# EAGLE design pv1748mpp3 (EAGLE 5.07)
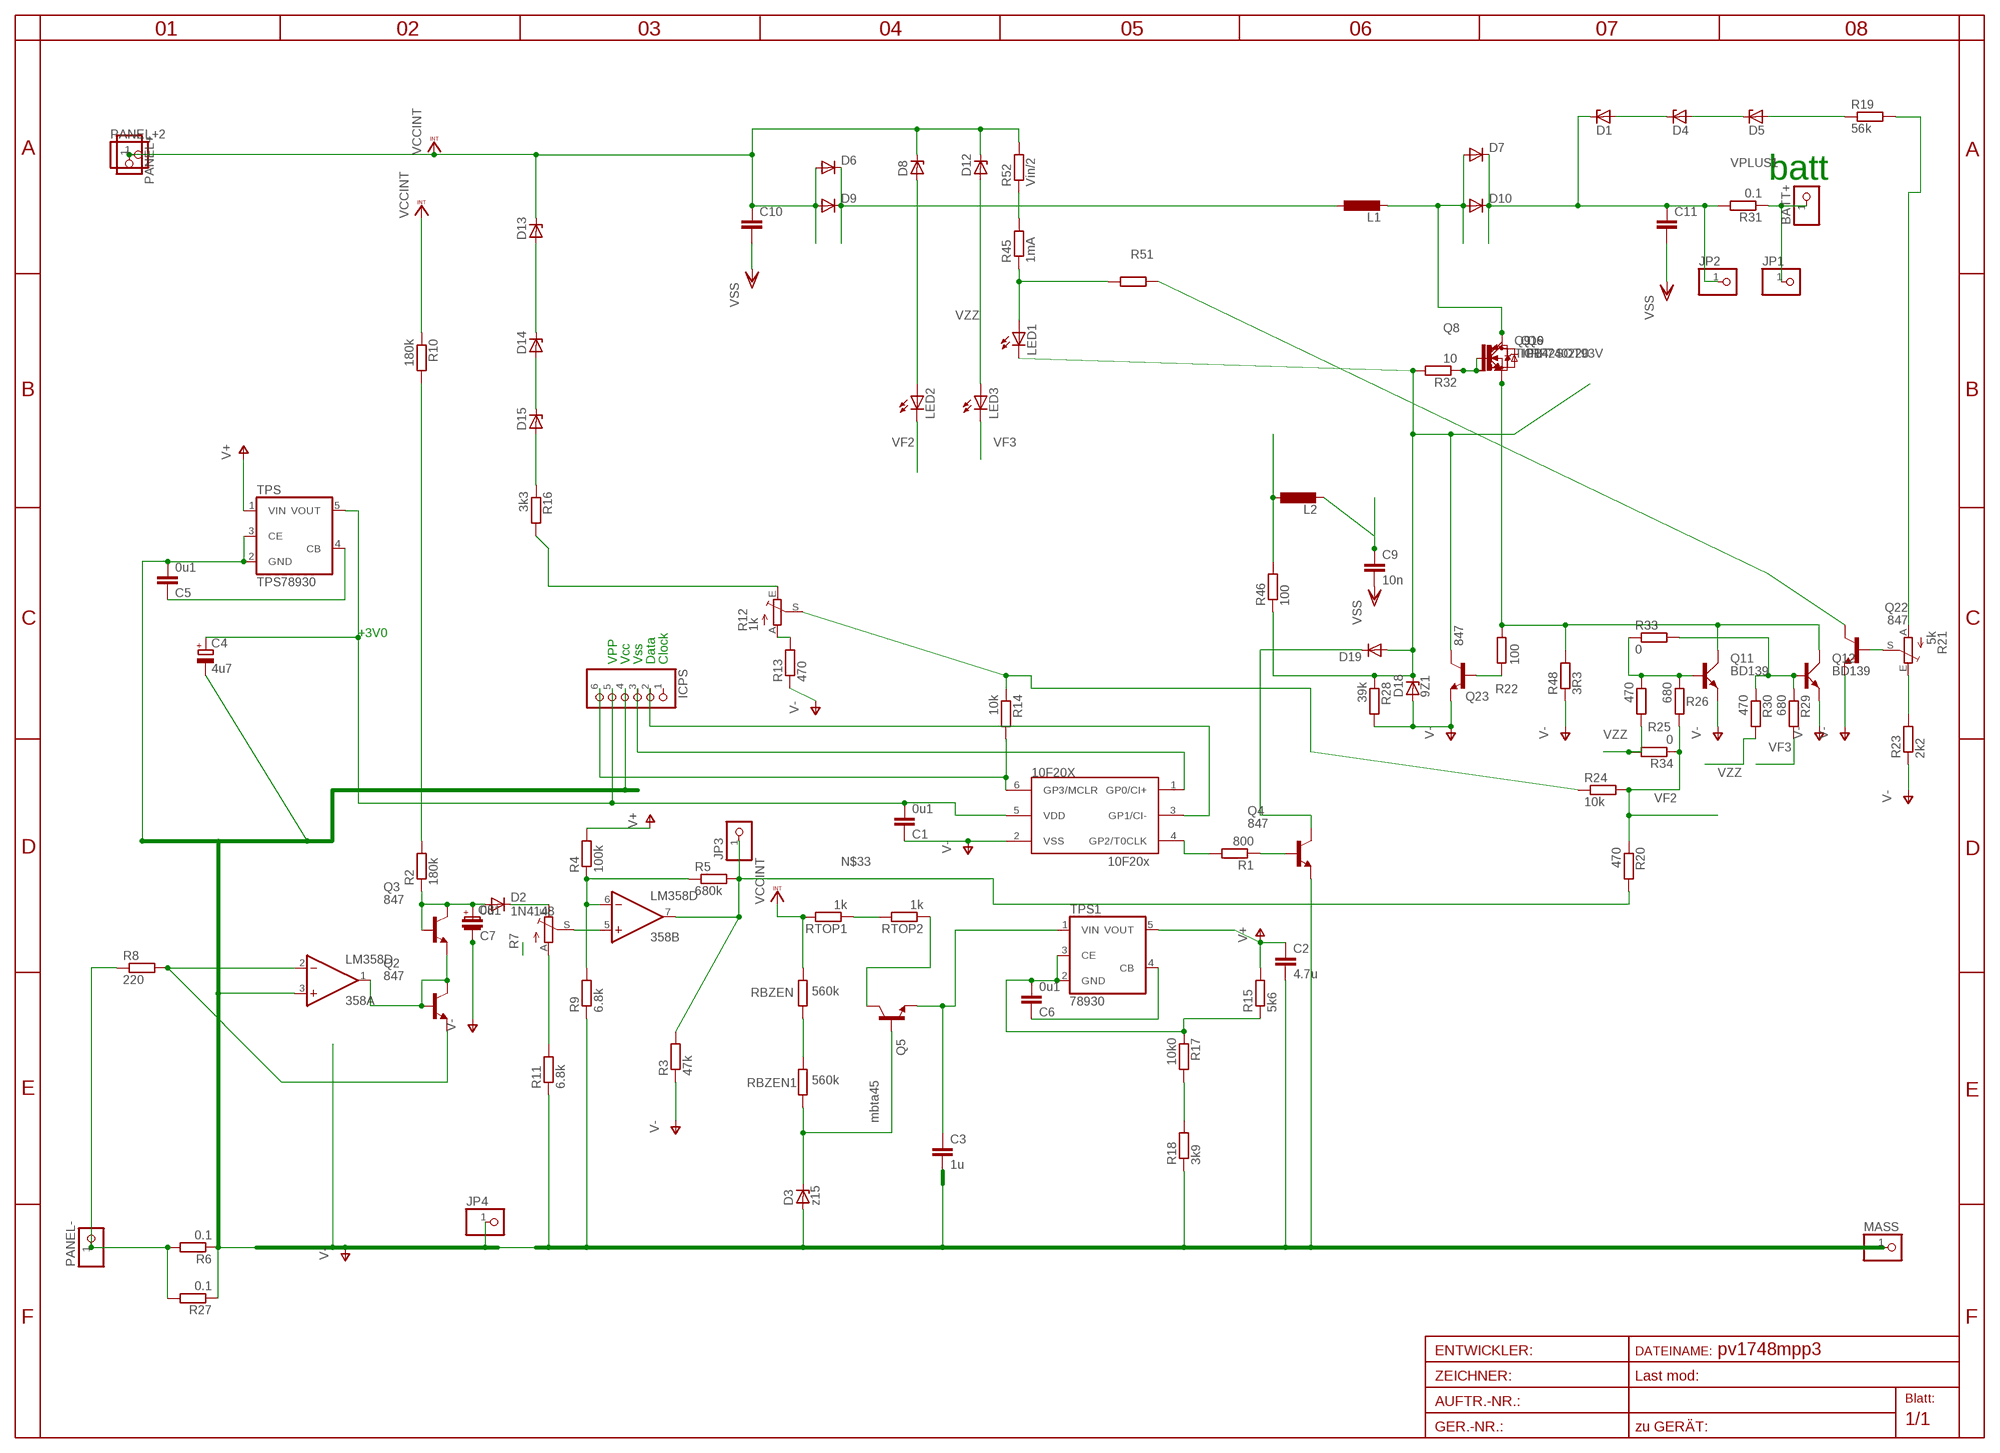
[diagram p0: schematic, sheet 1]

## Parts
10F20X  10F20x  PIC10F204OT  [SOT23-6]
358  LM358D  [SO08]
BATT+  PINHD-1X12MM3  [1X2MM3]
C1  0u1  C-EUC1206  [C1206]
C2  4.7u  C-EUC1206  [C1206]
C3  1u  C-EUC1206  [C1206]
C4  4u7  CPOL-EUSMCA  [SMC_A]
C5  0u1  C-EUC0805  [C0805]
C6  0u1  C-EUC0805  [C0805]
C7  0u1  C-EUC1608  [C1608]
C8  CPOL-EUSMCA  [SMC_A]
C9  10n  C-EUC0805  [C0805]
C10  C-EU075-052X106  [C075-052X106]
C11  C-EU075-052X106  [C075-052X106]
D1  ZENER-DIODESOD80C  [SOD80C]
D2  1N4148  DIODE-SOD80C  [SOD80C]
D3  z15  ZENER-DIODESOD80C  [SOD80C]
D4  ZENER-DIODESOD80C  [SOD80C]
D5  ZENER-DIODESOD80C  [SOD80C]
D6  DIODE-SMC  [SMC]
D7  DIODE-SMC  [SMC]
D8  ZENER-DIODESOD80C  [SOD80C]
D9  DIODE-SMC  [SMC]
D10  DIODE-SMC  [SMC]
D12  ZENER-DIODESOD80C  [SOD80C]
D13  ZENER-DIODESOD80C  [SOD80C]
D14  ZENER-DIODESOD80C  [SOD80C]
D15  ZENER-DIODESOD80C  [SOD80C]
D18  9Z1  ZENER-DIODESOD80C  [SOD80C]
D19  DIODE-MINIMELF  [MINIMELF]
ICPS  PINHD-1X6  [1X06BOX]
JP1  PINHD-1X11MM6  [1X1MM8]
JP2  PINHD-1X11MM6  [1X1MM8]
JP3  PINHD-1X11MM6  [1X1MM8]
JP4  PINHD-1X11MM6  [1X1MM8]
L1  L-EUOPEN6  [OPEN6_3]
L2  L-EUOPEN6  [OPEN6_3]
LED1  LEDCHIPLED_1206  [CHIPLED_1206]
LED2  LEDCHIPLED_1206  [CHIPLED_1206]
LED3  LEDCHIPLED_1206  [CHIPLED_1206]
MASS  PINHD-1X12MM3  [1X2MM3]
PANEL+  PINHD-1X11MM6  [1X1MM8]
PANEL+2  PINHD-1X12MM3  [1X2MM3]
PANEL-  PINHD-1X12MM3  [1X2MM3]
Q2  847  BC847ALT1SMD  [SOT23]
Q3  847  BC847ALT1SMD  [SOT23]
Q4  847  BC847ALT1SMD  [SOT23]
Q5  mbta45  BC847ALT1SMD  [SOT23]
Q6  IRF740220  [TO220BV]
Q8  IRG4BC15UD-S  [D2PACK]
Q9  TIP142SOT93V  [SOT93V]
Q11  BD139  [TO126AV]
Q12  BD139  [TO126AV]
Q19  IGBT  N-HEXFET_DPAK-  [TO252]
Q22  847  BC847ASMD  [SOT23]
Q23  847  BC847ASMD  [SOT23]
R1  800  R-EU_R0805  [R0805]
R2  180k  R-EU_0207/15  [0207/15]
R3  47k  R-EU_R0805  [R0805]
R4  100k  R-EU_R1206  [R1206]
R5  680k  R-EU_R0805  [R0805]
R6  0.1  R-EU_R1210  [R1210]
R7  TRIM_EU-S64W  [S64W]
R8  220  R-EU_R0805  [R0805]
R9  6.8k  R-EU_R1206  [R1206]
R10  180k  R-EU_R1206  [R1206]
R11  6.8k  R-EU_R0805  [R0805]
R12  1k  TRIM_EU-S64W  [S64W]
R13  470  R-EU_R0805  [R0805]
R14  10k  R-EU_R0805  [R0805]
R15  5k6  R-EU_R0805  [R0805]
R16  3k3  R-EU_R0805  [R0805]
R17  10k0  R-EU_R0805  [R0805]
R18  3k9  R-EU_R0805  [R0805]
R19  56k  R-EU_R0805  [R0805]
R20  470  R-EU_R0805  [R0805]
R21  5k  TRIM_EU-S64W  [S64W]
R22  100  R-EU_R0805  [R0805]
R23  2k2  R-EU_R0805  [R0805]
R24  10k  R-EU_R0805  [R0805]
R25  470  R-EU_R1206  [R1206]
R26  680  R-EU_R0805  [R0805]
R27  0.1  R-EU_R3216  [R3216]
R28  39k  R-EU_R0805  [R0805]
R29  680  R-EU_R0805  [R0805]
R30  470  R-EU_R0805  [R0805]
R31  0.1  R-EU_R1210  [R1210]
R32  10  R-EU_R0805  [R0805]
R33  0  R-EU_R0603  [R0603]
R34  0  R-EU_R0603  [R0603]
R45  1mA  R-EU_R0805  [R0805]
R46  100  R-EU_R0805  [R0805]
R48  3R3  R-EU_R1210  [R1210]
R51  39k  R-EU_R0805  [R0805]
R52  Vin/2  R-EU_R1206  [R1206]
RBZEN  560k  R-EU_R1206  [R1206]
RBZEN1  560k  R-EU_R1206  [R1206]
RTOP1  1k  R-EU_R1206  [R1206]
RTOP2  1k  R-EU_R1206  [R1206]
TPS  TPS78930  TPS78930SOT23-5  [SOT25]
TPS1  78930  TPS78930SOT23-5  [SOT25]

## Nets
BOOST_EN: D19.C Q4.3(C)
CB: D3.C Q5.1(B) RBZEN1.2
DQ18: D7.A D10.A L1.2 Q6.D Q8.2(C) Q9.C Q19.3(D)
GND1: C6.1 TPS1.4(CB)
IN-: PANEL-.1 R6.2 R8.1 R27.2
L1NO: D6.C D9.C L1.1
L2DOT: C9.1 L2.2
L2NO: L2.1 R46.2
N$1: Q4.1(B) R1.1
N$2: R7.A R11.2
N$3: R12.S R14.1 R24.1
N$4: 10F20X.1(GP0/CI+) ICPS.3
N$5: 10F20X.4(GP2/T0CLK) R1.2
N$6: R2.2 R10.2
N$7: 358.1(A:OUT) Q2.1(B) Q2.3(C) Q3.2(E)
N$8: 10F20X.3(GP1/CI-) ICPS.2
N$9: 10F20X.5(VDD) C1.2 C4.+ ICPS.5 TPS.5(VOUT)
N$10: 358.2(A:-IN) Q2.2(E) R8.2
N$11: C5.1 TPS.4(CB)
N$12: C7.2 C8.+ D2.A Q3.1(B) Q3.3(C) R2.1
N$13: D2.C R7.E
N$15: 358.5(B:+IN) R7.S
N$16: Q5.3(C) RTOP2.1
N$17: 358.6(B:-IN) R4.1 R5.1 R9.2
N$18: D15.A R16.1
N$19: RBZEN1.1 RBZEN.2
N$20: LED1.A R45.1 R51.1
N$21: Q23.1(B) R22.2
N$22: D5.A R19.1
N$23: D14.A D15.C
N$24: D13.A D14.C
N$25: R12.E R16.2
N$26: R12.A R13.2
N$27: R45.2 R52.1
N$28: R17.2 R18.2
N$29: RTOP1.1 RTOP2.2
N$30: D4.A D5.C
N$31: D1.A D4.C
N$32: R19.2 R21.A
N$33: 358.7(B:OUT) JP3.1 R3.2 R5.2 R20.2
N$34: R21.E R23.2
N$35: Q11.B R25.1 R26.1 R33.1
N$36: Q12.B R29.1 R30.1 R33.2
N$37: D8.A LED2.A
N$58: Q6.G Q8.1(G) Q9.B Q19.1(G) R32.1
N$71: Q22.3(C) R51.2
OUT+: BATT+.1 JP1.1 R31.1
PGATE: D18.C D19.A LED1.C Q23.3(C) R28.1 R32.2 R46.1
PIR: 10F20X.6(GP3/MCLR) ICPS.6 R14.2
PRB1: Q22.1(B) R21.S
SFET1: Q6.S Q8.3(E) Q9.E Q11.C Q12.C Q19.2(S) R22.1 R48.2
V15: C3.1 Q5.2(E) TPS1.1(VIN)
V+: C2.1 R4.2 R15.2 TPS1.5(VOUT) TPS.1(VIN)
V-: 10F20X.2(VSS) 358.3(A:+IN) C1.1 C2.2 C3.2 C4.- C5.2 C7.1 C8.- C9.2 C10.2 C11.2 D3.A D18.A ICPS.4 JP4.1 MASS.1 Q4.2(E) Q11.E Q12.E Q22.2(E) Q23.2(E) R3.1 R6.1 R9.1 R11.1 R13.1 R18.1 R23.1 R27.1 R28.2 R48.1 TPS.2(GND) TPS.3(CE) ; supply symbol labelled VSS
VCCINT: C10.1 D6.A D8.C D9.A D12.C D13.C PANEL+2.1 PANEL+.1 R10.1 R52.2 RBZEN.1 RTOP1.2
VF2: LED2.C R20.1 R24.2 R26.2 R34.1
VF3: LED3.C R29.2
VPLUS1: C11.1 D1.C D7.C D10.C JP2.1 R31.2
VZZ: D12.A LED3.A R25.2 R30.2 R34.2
X: C6.2 R15.1 R17.1 TPS1.2(GND) TPS1.3(CE)
Unconnected: ICPS.1

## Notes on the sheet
- batt
- +3V0
- VPP | Vcc | Vss | Data | Clock

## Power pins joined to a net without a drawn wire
V+: 358.8(P:V+)
V-: 358.4(P:V-)

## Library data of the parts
10F20X = microchip-3:PIC10F2*: uPC nW 0,25/0,5k Program Flash memory Comparator
358 = linear:LM358: OP AMP also LM158; LM258; LM2904 Source: http://cache.national.com/ds/LM/LM158.pdf
BATT+ JP1-JP4 MASS PANEL+ PANEL+2 PANEL- = pinhead:PINHD-1X1: PIN HEADER
C1-C3 C5-C7 C9-C11 = rcl:C-EU: CAPACITOR, European symbol
C4 = rcl(2):CPOL-EU: POLARIZED CAPACITOR, European symbol
C8 = rcl:CPOL-EU: POLARIZED CAPACITOR, European symbol
D1 D3-D5 D8 D12-D15 D18 = diode:ZENER-DIODE: Z-Diode
D2 D6 D7 D9 D10 D19 = diode:DIODE-: DIODE
ICPS = pinhead:PINHD-1X6: PIN HEADER
L1 L2 = rcl:L-EU: INDUCTOR, European symbol
LED1-LED3 = led:LED: LED
Q2-Q5 Q22 Q23 = transistor-npn:BC847*: NPN Transistor
Q6 = transistor-power:IRF740: N-CHANNEL MOS FET
Q8 = transistor-power:IRG4BC15UD-: INSULATED GATE BIPOLAR TRANSISTOR WITH ULTRAFAST SOFT RECOVERY DIODE
Q9 = transistor-power:TIP142: NPN DARLINGTON TRANSISTOR
Q11 Q12 = transistor-power:BD139: NPN TRANSISTOR
Q19 = transistor-power:N-HEXFET_?-*: HEXFET® Power MOSFET
R1-R6 R8-R11 R13-R20 R22-R31 R33 R34 RBZEN RBZEN1 RTOP1 RTOP2 = rcl:R-EU_: RESISTOR, European symbol
R7 R12 R21 = pot:TRIM_EU-: POTENTIOMETER
R32 R45 R46 R48 R51 R52 = rcl-2:R-EU_: RESISTOR, European symbol
TPS TPS1 = v-reg:TPS78930

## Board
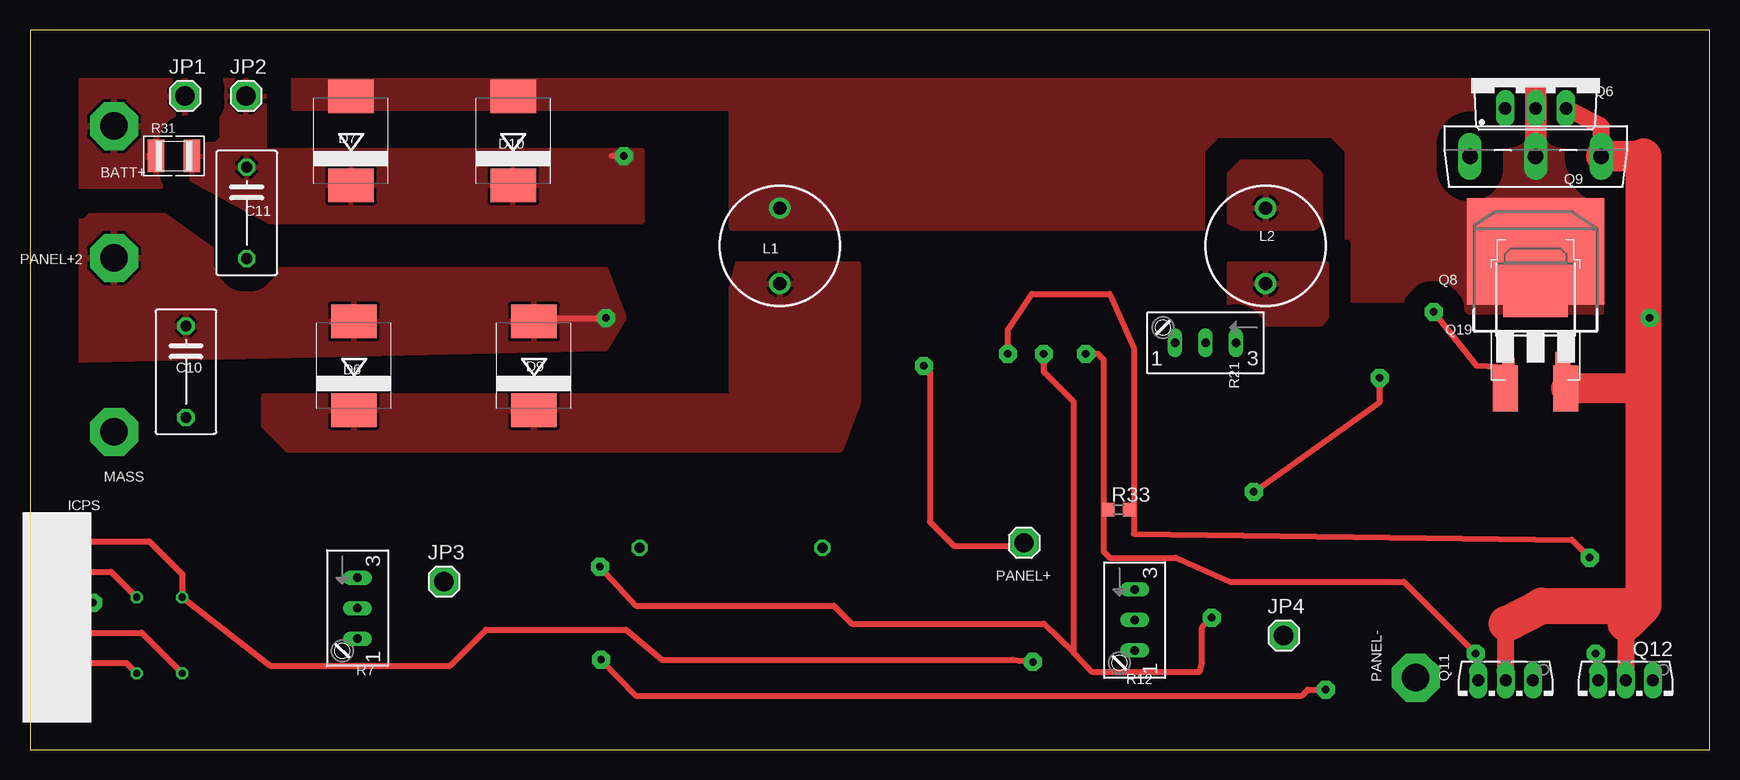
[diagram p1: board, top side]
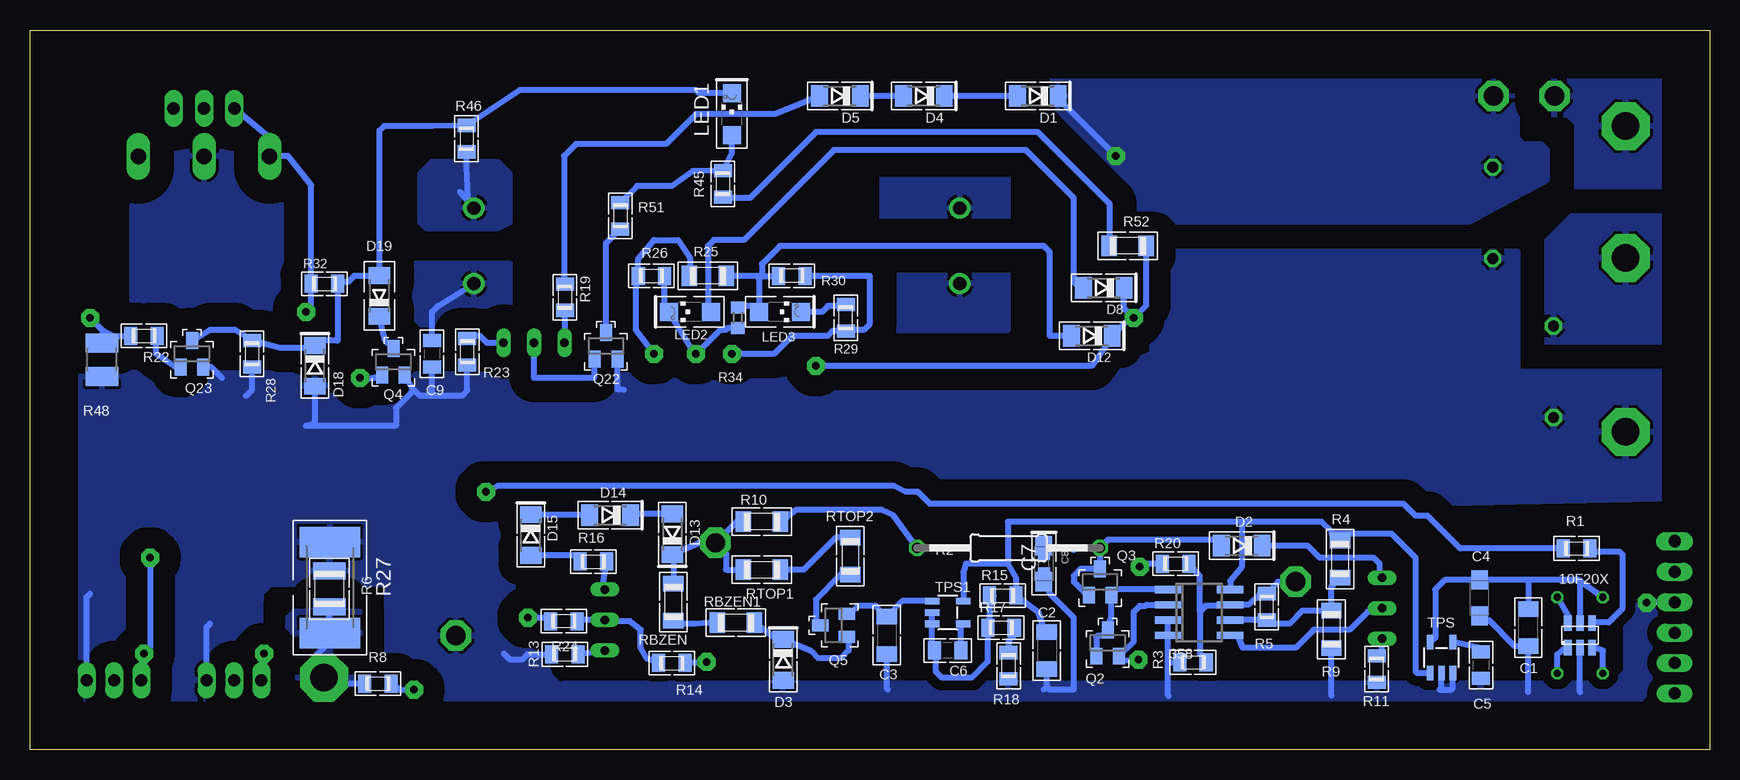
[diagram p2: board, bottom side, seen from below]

Size 140 x 60 mm. Coordinates in mm from the lower left corner, seen from the top.
Outline: 0,0 140,0 140,60 0,60 0,0
Copper layers (1*16): Top 0.035mm / dielectric 1.5mm / Bottom 0.035mm
Design rules "default *": minimum track width 10mil, minimum drill 24mil, track to track 8mil, track to pad 8mil, pad to pad 8mil, via to via 8mil, smd to smd 8mil, copper to edge 4mm, drill to drill 8mil, minimum pad ring 10mil, minimum via ring 8mil, stop-mask expansion 4mil, vias tented up to drill 0mil, thermal gap 10mil

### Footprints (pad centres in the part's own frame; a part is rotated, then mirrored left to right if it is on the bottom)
SOT23-6 = smd 0.635 x 1.27: 1 -1.016,-1.016; 2 0,-1.016; 3 1.016,-1.016; 4 1.016,1.016; 5 0,1.016; 6 -1.016,1.016
SO08 = smd 0.6 x 2.2: 1 -1.905,-2.6; 2 -0.635,-2.6; 3 0.635,-2.6; 4 1.905,-2.6; 5 1.905,2.6; 6 0.635,2.6; 7 -0.635,2.6; 8 -1.905,2.6
1X2MM3 = drill 2.3 pad 4 octagon: 1 0,0
C1206 = smd 1.3 x 1.7: 1 -1.55,0; 2 1.55,0
SMC_A = smd 1.6 x 1.4: + -1.5,0; - 1.5,0
C0805 = smd 1.1 x 1.5: 1 -1.1,0; 2 1.1,0
C1608 = smd 1.1 x 1: 1 -0.85,0; 2 0.85,0
C075-052X106 = drill 0.914 octagon: 1 -3.81,0; 2 3.81,0
SOD80C = smd 1.4 x 1.8: A 1.7,0; C -1.7,0
SMC = smd 2.8 x 3.8: A 3.7,0; C -3.7,0
MINIMELF = smd 1.4 x 1.8: A 1.7,0; C -1.7,0
1X06BOX = drill 1 long: 1 -6.35,0; 2 -3.81,0; 3 -1.27,0; 4 1.27,0; 5 3.81,0 | drill 1.016 long: 6 6.35,0
1X1MM8 = drill 1.6 pad 2.54 octagon: 1 0,0
OPEN6_3 = drill 1.1 pad 1.778 round: 1 -3.15,0; 2 3.15,0
CHIPLED_1206 = smd 1.5 x 1.5: A 0,-1.75; C 0,1.75
SOT23 = smd 1 x 1.4: 1 -0.95,-1.1; 2 0.95,-1.1; 3 0,1.1
TO220BV = drill 1.016 long: D 0,-2.54; G -2.54,-2.54; S 2.54,-2.54
D2PACK = smd 2.083 x 3.81: 1 -2.54,-8.89; 3 2.54,-8.89 | smd 11.43 x 8.89: 2 0,2.54
SOT93V = drill 1.3 pad 1.676 long: B -5.461,-2.54; C 0,-2.54; E 5.461,-2.54
TO126AV = drill 1 pad 1.27 long: B 2.286,-1.27; C 0,-1.27; E -2.286,-1.27
TO252 = smd 1 x 1.6: 1 -2.28,-3.53 | smd 1.27 x 2.54: 2 2.28,-3.53 | smd 5.4 x 6.2: 3 0,3.77
R0805 = smd 1.1 x 1.5: 1 -1.1,0; 2 1.1,0
0207/15 = drill 0.813 octagon: 1 -7.62,0; 2 7.62,0
R1206 = smd 1.3 x 1.7: 1 -1.55,0; 2 1.55,0
R1210 = smd 1.4 x 2.7: 1 -1.5,0; 2 1.5,0
S64W = drill 0.7 long: A 2.54,1.27; E -2.54,1.27; S 0,1.27
R3216 = smd 2.54 x 5.08: 1 -3.81,0; 2 3.81,0
R0603 = smd 1 x 1.1: 1 -0.85,0; 2 0.85,0
R1210' = smd 1.6 x 2.7: 1 -1.4,0; 2 1.4,0
SOT25 = smd 0.55 x 1.2: 1 -0.95,-1.3; 2 0,-1.3; 3 0.95,-1.3; 4 0.95,1.3; 5 -0.95,1.3

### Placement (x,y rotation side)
10F20X  10.79,9.53 0 bottom
358  42.55,11.43 270 bottom
BATT+  7,52 0 top
C1  15.11,10.16 90 bottom
C2  55.24,8.26 270 bottom
C3  68.58,9.53 270 bottom
C4  19.18,12.63 270 bottom
C5  19.05,7.04 270 bottom
C6  63.5,8.26 180 bottom
C7  55.5,15.5 90 bottom
C8  55.5,15.5 270 bottom
C9  106.5,33 270 bottom
C10  13,31.5 270 top
C11  18.07,44.75 270 top
D1  56,54.5 180 bottom
D2  39,17 180 bottom
D3  77.22,7.48 270 bottom
D4  65.5,54.5 180 bottom
D5  72.5,54.5 180 bottom
D6  27,32 90 top
D7  26.77,50.75 90 top
D8  50.5,38.5 180 bottom
D9  42,32 90 top
D10  40.29,50.75 90 top
D12  51.5,34.5 180 bottom
D13  86.45,17.96 90 bottom
D14  91.65,19.55 180 bottom
D15  98.27,17.88 270 bottom
D18  116.25,32 270 bottom
D19  110.88,37.83 90 bottom
ICPS  2.9,11.02 90 top
JP1  12.92,54.5 0 top
JP2  18,54.5 0 top
JP3  34.5,14 0 top
JP4  104.5,9.5 0 top
L1  62.5,42 90 top
L2  103,42 270 top
LED1  81.5,53 0 bottom
LED2  85,36.5 90 bottom
LED3  77.5,36.5 270 bottom
MASS  7,26.5 0 top
PANEL+  82.86,17.24 0 top
PANEL+2  7,41 0 top
PANEL-  115.5,6 90 top
Q2  50.16,8.89 0 bottom
Q3  50.8,13.97 0 bottom
Q4  109.7,32.33 0 bottom
Q5  73.03,10.35 90 bottom
Q6  125.5,56 0 top
Q8  125.5,39 0 top
Q9  125.5,52 0 top
Q11  123,4.5 180 top
Q12  133,4.5 180 top
Q19  125.5,35.4 0 top
Q22  91.99,33.66 0 bottom
Q23  126.5,33 0 bottom
R1  11.08,16.77 0 bottom
R2  58.44,16.81 180 bottom
R3  43.05,7.27 0 bottom
R4  30.8,15.88 90 bottom
R5  36.9,11.9 90 bottom
R6  115.06,13.39 270 bottom
R7  26.04,11.79 270 top
R8  111,5.5 0 bottom
R9  31.52,10.03 90 bottom
R10  79,19 0 bottom
R11  27.75,6.71 90 bottom
R12  90.81,10.79 270 top
R13  95.42,7.94 0 bottom
R14  86.5,7.21 0 bottom
R15  58.92,12.84 0 bottom
R16  93.05,15.68 0 bottom
R17  59.05,10.16 0 bottom
R18  58.42,6.99 90 bottom
R19  95.41,37.72 270 bottom
R20  44.5,15.5 0 bottom
R21  97.99,35.18 180 top
R22  130.5,34.5 0 bottom
R23  103.55,33.16 90 bottom
R24  95.5,10.7 180 bottom
R25  83.5,39.5 0 bottom
R26  88.2,39.5 0 bottom
R27  115,13.5 270 bottom
R28  121.5,33 270 bottom
R29  72,36 90 bottom
R30  76.5,39.5 180 bottom
R31  12,49.5 0 top
R32  115.45,38.84 0 bottom
R33  90.75,20 0 top
R34  81,36 90 bottom
R45  82.25,47.17 270 bottom
R46  103.61,50.94 270 bottom
R48  3R3  [R1210']  134,32.5 90 bottom
R51  90.8,44.5 270 bottom
R52  48.5,42 0 bottom
RBZEN  86.36,12.29 270 bottom
RBZEN1  81.16,10.57 0 bottom
RTOP1  79,15 180 bottom
RTOP2  71.62,16.12 90 bottom
TPS  22.35,7.67 0 bottom
TPS1  63.5,11.43 270 bottom

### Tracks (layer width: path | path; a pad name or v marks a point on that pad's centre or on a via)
BOOST_EN
  Bottom 0.5: D19.C 110.39,34.12 Q4.3
CB
  Bottom 0.5: Q5.1 71.75,9.23 71.75,8.26 72.39,7.62 74.3,7.62 74.85,8.18 D3.C 77.72,9.18 RBZEN1.2
DQ18
  Top 1.8: Q9.C Q6.D 125.5,55
  pour Top (isolate 1.8, rank 4, no thermals): 22,53.5 22,58 128.5,58.5 137,36.5 118,36.5 117,37.5 107.5,37.5 107.5,43.5 58.5,43.5 58.5,53.5
  pour Bottom (isolate 2): 119,51 130,51 131.5,49.5 131.5,37 131,36.5 119,36.5 118,37.5
  pour Bottom (isolate 2): 58.5,49.5 69,49.5 69,43.5 58.5,43.5
GND1
  Bottom 0.5: C6.1 62.4,10.28 TPS1.4
IN-
  Bottom 0.5: R6.2 115.06,8.95 116.33,7.68 PANEL-.1 115.5,5.5 R8.1
  pour Bottom (isolate 2): 119,2 114,2 112.5,3.5 112.5,11.5 118,11.5 118.5,11
L1NO
  pour Top (isolate 2, rank 3): 19.5,29.5 58.5,29.5 58.5,38.5 59,40.5 69,40.5 69,29 67.5,25 21.5,25 19.5,27
  pour Bottom (isolate 2): 58.5,40.5 69,40.5 69,35.5 68.5,35 58.5,35
L2DOT
  Bottom 0.5: C9.1 106.5,36.5 106,37 L2.2
  pour Bottom (isolate 2): 100,40.5 108,40.5 108,36 107.5,35.5 101,35.5 100,36.5
  pour Top (isolate 2): 100,40.5 108,40.5 108,39 108,36 107.5,35.5 101,35.5 100,36.5
L2NO
  Bottom 0.5: R46.2 103.61,48.61 103.5,46 104.15,46.5 L2.1
  pour Bottom (isolate 2): 100,44 100,48 101,49 106.5,49 107.5,48 107.5,44 107,43.5 101,43.5
  pour Top (isolate 2): 100,44 100,48 101,49 106.5,49 107.5,48 107.5,44 107,43.5 101,43.5
N$1  (via drill 0.6 pad 1.5)
  Top 0.5: v102,21.5 112.5,29 v112.5,31
  Bottom 0.5: R1.1 20.77,16.77 23.5,19.5 24.5,19.5 25.5,20.5 65,20.5 66,21.5 67,21.5 68,22 101,22 v102,21.5 | v112.5,31 111.39,31 Q4.1
N$2
  Bottom 0.5: R7.A 27.3,8.26 R11.2
N$3
  Bottom 0.5: R14.1 88.59,7.59 89.1,8.5 89.1,10 90,10.7 91.87,10.7 R12.S 94,10.8 R24.1
N$4  (via drill 0.6)
  Top 0.5: ICPS.3 9.3,9.75 v12.7,6.35
  Bottom 0.5: v12.7,6.35 12.7,7.9 11.99,8.51 10F20X.1
N$5
  Bottom 0.5: 10F20X.4 9.72,10.6 8.4,10.6 7.24,11.76 7.24,16.24 7.5,16.5 9.71,16.5 R1.2
N$6
  Bottom 0.5: R2.2 68.06,19.56 69,20 76.14,20 R10.2
N$7
  Bottom 0.5: 358.1 49.38,13.34 Q3.2 49.9,12.42 49.9,10.9 50.16,10.34 Q2.3 50.66,9.5 51,9.5 51.12,9.38 Q2.1
N$8  (via drill 0.6)
  Top 0.5: ICPS.2 8.03,7.21 v8.89,6.35
  Bottom 0.5: v8.89,6.35 8.89,8.26 10F20X.3
N$9  (via drill 0.6)
  Top 0.5: ICPS.5 6.76,14.83 v8.89,12.7
  Bottom 0.5: 15.24,14.13 10.86,14.13 10.75,14.02 | 15.24,14.13 C4.+ 22.06,14.13 22.86,13.34 22.86,9.3 TPS.5 | v8.89,12.7 10.7,13.97 10.75,14.02 | 10F20X.5 10.79,13.97 10.75,14.02 | C1.2 15.11,14 15.24,14.13
N$10  (via drill 0.6 pad 1.5)
  Top 0.5: v108,5 106.5,5 106,4.5 50.5,4.5 v47.6,7.5
  Bottom 0.5: 358.2 46.94,12.06 47,12 47.5,12 48,11.5 48,9 Q2.2 49.1,7.41 v47.6,7.5 | R8.2 109.08,4.92 v108,5
N$11
  Bottom 0.5: TPS.4 19.25,8.47 C5.1
N$12
  Bottom 0.5: D2.A 41,17.5 50.13,17.5 R2.1 | R2.1 52.82,16.78 53.12,16.73 | Q3.1 51.87,12.87 53,14 53,14.5 52.43,15.07 Q3.3 50.82,15.09 R2.1 | 53.12,16.73 53,16.62 | C7.2 C8.+ 55.23,16.73 53.12,16.73
N$13
  Bottom 0.5: D2.C 33.49,16.99 32.5,16 28,16 27.5,15.5 27.5,14.03 R7.E
N$15
  Bottom 0.5: 358.5 39.33,9.53 38.9,8.5 34.5,8.5 33,10 30,10 28.5,11.5 27.59,11.5 R7.S
N$16
  Bottom 0.5: RTOP2.1 72.43,14.57 74.5,12.5 74.5,10.73 Q5.3
N$17
  Bottom 0.5: R4.1 31.52,13.55 R9.2 33.92,11.57 35,10.5 36.59,10.5 R5.1 37.91,10.79 358.6
N$18
  Bottom 0.5: D15.A 94.66,16.18 R16.1
N$19
  Bottom 0.5: RBZEN1.1 83.37,10.57 84.5,10.5 85.61,10.5 RBZEN.2
N$20
  Bottom 0.5: R51.1 89.4,47 86.5,47 84.75,48.25 R45.1 81.5,49.72 LED1.A
N$21
  Bottom 0.5: Q23.1 127.9,31.9 129.5,33 129.5,34.6 R22.2
N$22
  Bottom 0.5: D5.A 77.91,53 84.5,53 87,50.5 94.5,50.5 95.5,49.5 95.5,38.91 R19.1
N$23
  Bottom 0.5: D14.A 98.23,19.55 D15.C
N$24
  Bottom 0.5: D13.A 89.84,19.66 D14.C
N$25
  Bottom 0.5: R16.2 92.25,13.76 R12.E
N$26
  Bottom 0.5: R13.2 92.94,8.12 R12.A
N$27
  Bottom 0.5: R52.1 50,42.5 50,45.5 56,51.5 74.5,51.5 80,46 82.37,46 R45.2
N$28
  Bottom 0.5: R18.2 58.42,9.08 58,9.5 58,10.12 R17.2
N$29
  Bottom 0.5: RTOP1.1 75.52,14.98 72.83,17.67 RTOP2.2
N$30
  Bottom 0.5: D4.A D5.C
N$31
  Bottom 0.5: D1.A D4.C
N$32
  Bottom 0.5: R19.2 95.41,33.95 R21.A
N$33
  Bottom 0.5: R3.2 42.05,7.54 42.5,8 42.5,11.5 | 42.5,11.5 42,12 40.01,12 358.7 38.44,12.06 37.5,13 R5.2 35.95,14 JP3.1 | 42.5,11.5 42.5,14.5 43,15 43,15.1 R20.2
N$34
  Bottom 0.5: R21.E 101.91,33.91 102.5,34.5 103.31,34.5 R23.2
N$35  (via drill 0.6 pad 1.5)
  Top 0.5: v120.5,8 114.5,14 100,14 95.5,16 90,16 89.5,16.5 89.5,20 | 89.5,20 89.5,32.5 89,33 v88,33 | 89.5,20 R33.1
  Bottom 0.5: Q11.B 120.5,5.77 v120.5,8 | v88,33 89.5,35 89.5,38.5 R26.1 89.3,40.9 88,42.5 86,42.5 85,41 85,39.55 R25.1
N$36  (via drill 0.6 pad 1.5)
  Top 0.5: v81.5,33 81.5,35 83.5,38 90,38 92,33.5 92,20 | 92,20 92,18 128.5,17.5 v130,16 | 92,20 R33.2
  Bottom 0.5: Q12.B 130.5,5.77 v130.5,8 130,8.5 v130,16 | 72.5,34.9 R29.1 | 72.5,34.9 73.1,34.9 73.5,34.5 76.5,34.5 78,33 v81.5,33 | R30.1 70,39.5 70,35.5 70.5,35 72.4,35 72.5,34.9
N$37
  Bottom 0.5: D8.A 52.5,38.5 53,39 53,46 57,50 73,50 80.5,42.5 83,42.5 83.5,42 83.5,36.75 LED2.A
N$58  (via drill 0.6 pad 1.5)
  Top 0.406: Q9.B 119.46,49.46 | Q8.1 122.96,31.61 Q19.1
  Top 0.5: v117,36.5 120.59,32 Q19.1
  Bottom 0.5: Q6.G 120.04,51.04 Q9.B 120,49.5 118.5,49.5 116.56,47.05 R32.1 116.56,36.45 v117,36.5
N$71
  Bottom 0.5: Q22.3 91.99,42.21 R51.2
OUT+
  pour Bottom (isolate 2, rank 2): 0.5,58.5 14,58.5 14,48 12,47 0.5,47
  pour Top (isolate 2, rank 2): 0.5,58.5 14,58.5 14,48 12,47 0.5,47
PGATE
  Bottom 0.5: Q23.3 126.4,34.1 125,35 122.9,35 R28.1 119.15,33.5 116,33.5 116.2,33.7 D18.C 115.86,34.09 114.36,34.09 R32.2 114.16,38.84 114,39 113.5,39 113,39.5 110.91,39.5 D19.A 110.88,51.62 110.5,52 106.46,52 R46.1 99.15,55 84.5,55 84.25,54.75 LED1.C
PIR  (via drill 0.6, 0.6 pad 1.5)
  Top 0.5: v83.6,7.3 81.92,7.48 52.67,7.48 49.67,10 38,10 35,7 20.04,7 v12.7,12.7 12.7,14.61 9.94,17.37 ICPS.6
  Bottom 0.5: 10F20X.6 11.81,11.18 v12.7,12.7 | R14.2 84.58,7.21 v83.6,7.3
PRB1
  Bottom 0.5: R21.S 97.99,31.01 98,31 93,31 93,32.5 Q22.1
SFET1  (via drill 0.6 pad 1.5)
  Top 0.406: 123.1,10.5 123.1,10 123,10 | 128.04,30 Q8.3 127.78,30.37 Q19.2 | 134.5,36 v135,36
  Top 1.4: 133,10.5 Q12.C | Q11.C 123,10 | Q6.S 130.96,51.96 Q9.E
  Top 2.5: 134.5,30.11 Q8.3
  Top 2.54: 134.5,49.46 Q9.E
  Top 3: 123.1,10.5 126,12 134.5,12 | 134.5,12 133,10.5 | 134.5,12 134.5,29.5 134.5,30.11 134.5,36 134.5,49.46
  Bottom 0.5: 134,35 R48.2 | v135,36 134,35 | R22.1 133,34.5 134,35
V15
  Bottom 0.5: TPS1.1 67.28,12.38 C3.1 69.5,12 71,12 71.7,11.3 Q5.2
V+
  Bottom 0.5: TPS.1 24.38,6.38 24.5,6.5 24.5,16 26.5,18 31.5,18 31.5,18.18 | 31.5,18.18 R4.2 | 39,19 32.32,19 31.5,18.18 | 39,19 58.5,19 58.5,15.5 | C2.1 55.24,9.74 55.5,10 56,11.5 R15.2 57.82,14.32 58.5,15.5 | TPS1.5 62.2,14.8 62,15.5 58.5,15.5 | 358.8 39.95,14.05 39,15.25 39,19
V-  (via drill 0.6 pad 1.5)
  Top 0.5: ICPS.4 5.21,12.29 v5.25,12.25
  Bottom 0.5: 15.11,4.81 C1.1 16.23,8.62 18.41,10.79 18.84,10.79 C4.- | 10.79,4.81 10F20X.2 | 45.15,7.27 45.15,4.5 45.09,4.45 | 358.3 358.4 45.15,7.27 | v5.25,12.25 4.54,12.25 ICPS.4 | R9.1 31.52,4.53 31.5,4.5 | Q23.2 124.9,31.9 124,31 | R28.2 121.5,30 122,29.5 | Q22.2 91.04,30.04 90.5,30 | D18.A 116.25,27.25 117,27 109.5,27 109.5,28.5 108,30 | 108,30 108.03,30 Q4.2 | 106.5,29.5 C9.2 | 106.5,29.5 107.5,29.5 108,30 | R23.1 103.55,29.95 104,29.5 106.5,29.5 | C3.2 68.58,5.08 68.5,5 | 55.24,5.25 C2.2 | 55.24,5.25 55.5,5 | R13.1 98.56,7.94 99,7.5 100,7.5 100.5,8 | Q12.E 135.29,12.71 135,13 | Q11.E 125.29,10.21 125,10.5 | TPS.3 21.4,5.1 21.5,5 22.5,5 22.35,5.15 TPS.2 | 55.24,5.25 54.99,5 53,5 53,11 55,13 C7.1 C8.- | 45.15,7.27 R3.1
  pour Bottom (isolate 1.8, rank 2): 95.5,2.5 95.5,19 2.5,21 2.5,31.5 16,31.5 16,41.5 46.5,41.5 46.5,33 51.5,31 139,31.5 139.22,2
  pour Bottom (isolate 0.813): 1.5,12.5 6.5,12 7,11.5 7,6.5 8,5.5 95.5,5.5 96.5,4.5 96.5,3.5 95,2 8,2 5,5 5,9
VCCINT  (via drill 0.6 pad 1.5)
  Top 0.5: v48,36 42.3,36 D9.A | PANEL+.1 82.62,17 77,17 75,19 75,31.5 v74.5,32
  Bottom 0.5: PANEL+.1 83.86,17.34 D13.C 86.36,16.16 RBZEN.1 | C10.1 13,35.5 | PANEL+.1 82,16.38 82,15 RTOP1.2 | PANEL+.1 81.1,19 R10.1 | v74.5,32 51.5,32 50.3,33.7 49.8,34.2 D12.C 48.3,36 v48,36 | R52.2 46.95,37.05 v48,36 | D8.C 48.8,36.8 v48,36
  pour Top (isolate 2, rank 3): 48,33.5 49.5,36 48,40 17.5,40 10.5,45 5.5,45 4.5,44 3,44.5 3,32.5
  pour Bottom (isolate 2, rank 3): 2,45 11,45 15,41 15,34 13.5,32.5 2.5,32.5 2,33
VF2  (via drill 0.6 pad 1.5)
  Top 0.5: v47.5,15.25 50.5,12 67,12 68.5,10.5 84.5,10.5 87,8.05 | 87,8.05 88.5,6.5 97.5,6.5 97.7,7.2 97.7,10.2 v98.5,11 | v84.5,33 84.5,31.5 87,29 87,8.05
  Bottom 0.5: v98.5,11 96.9,11 R24.2 | R26.2 87.1,37.15 LED2.C 84.75,33.25 v84.5,33 82.5,35 82,35 81.85,35.15 R34.1 | R20.1 47.25,15.5 v47.5,15.25
VF3
  Bottom 0.5: LED3.C 74,36.5 73.5,37 72.1,37 R29.2
VPLUS1  (via drill 0.6 pad 1.5)
  Top 0.5: v49.5,49.5 48.5,49.5
  Bottom 0.5: D1.C 54,54 v49.5,49.5
  pour Top (isolate 2): 16,56 19.5,56.5 19.5,50 51,50 51,44 20,44 13.5,47.5 13.5,50 14,50.5 15.5,50.5 16,51
  pour Bottom (isolate 2): 16,56 19.5,56.5 24.5,57 56,57 51,44 20,44 13.5,47.5 13.5,50 14,50.5 15.5,50.5 16,51
VZZ
  Bottom 0.5: 79,39.5 R30.2 | 79,39.5 R25.2 | 79,39.5 79.25,39.25 LED3.A 79.25,36.75 79.5,37 80.85,37 R34.2 | D12.A 55,34.5 55,41.5 55.5,42 77.5,42 79,40.5 79,39.5
X
  Bottom 0.5: R15.1 59.66,12.84 60,12 60,11.01 R17.1 60.16,7.34 61.5,6 64,6 64.5,6.5 64.5,8.15 C6.2 64.8,8.46 TPS1.3 TPS1.2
